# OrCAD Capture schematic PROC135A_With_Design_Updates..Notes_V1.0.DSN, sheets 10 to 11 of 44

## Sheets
10 10. PERIPHERAL POWER SUPPLY-1: size C; title: PERIPHERAL POWER SUPPLY -1
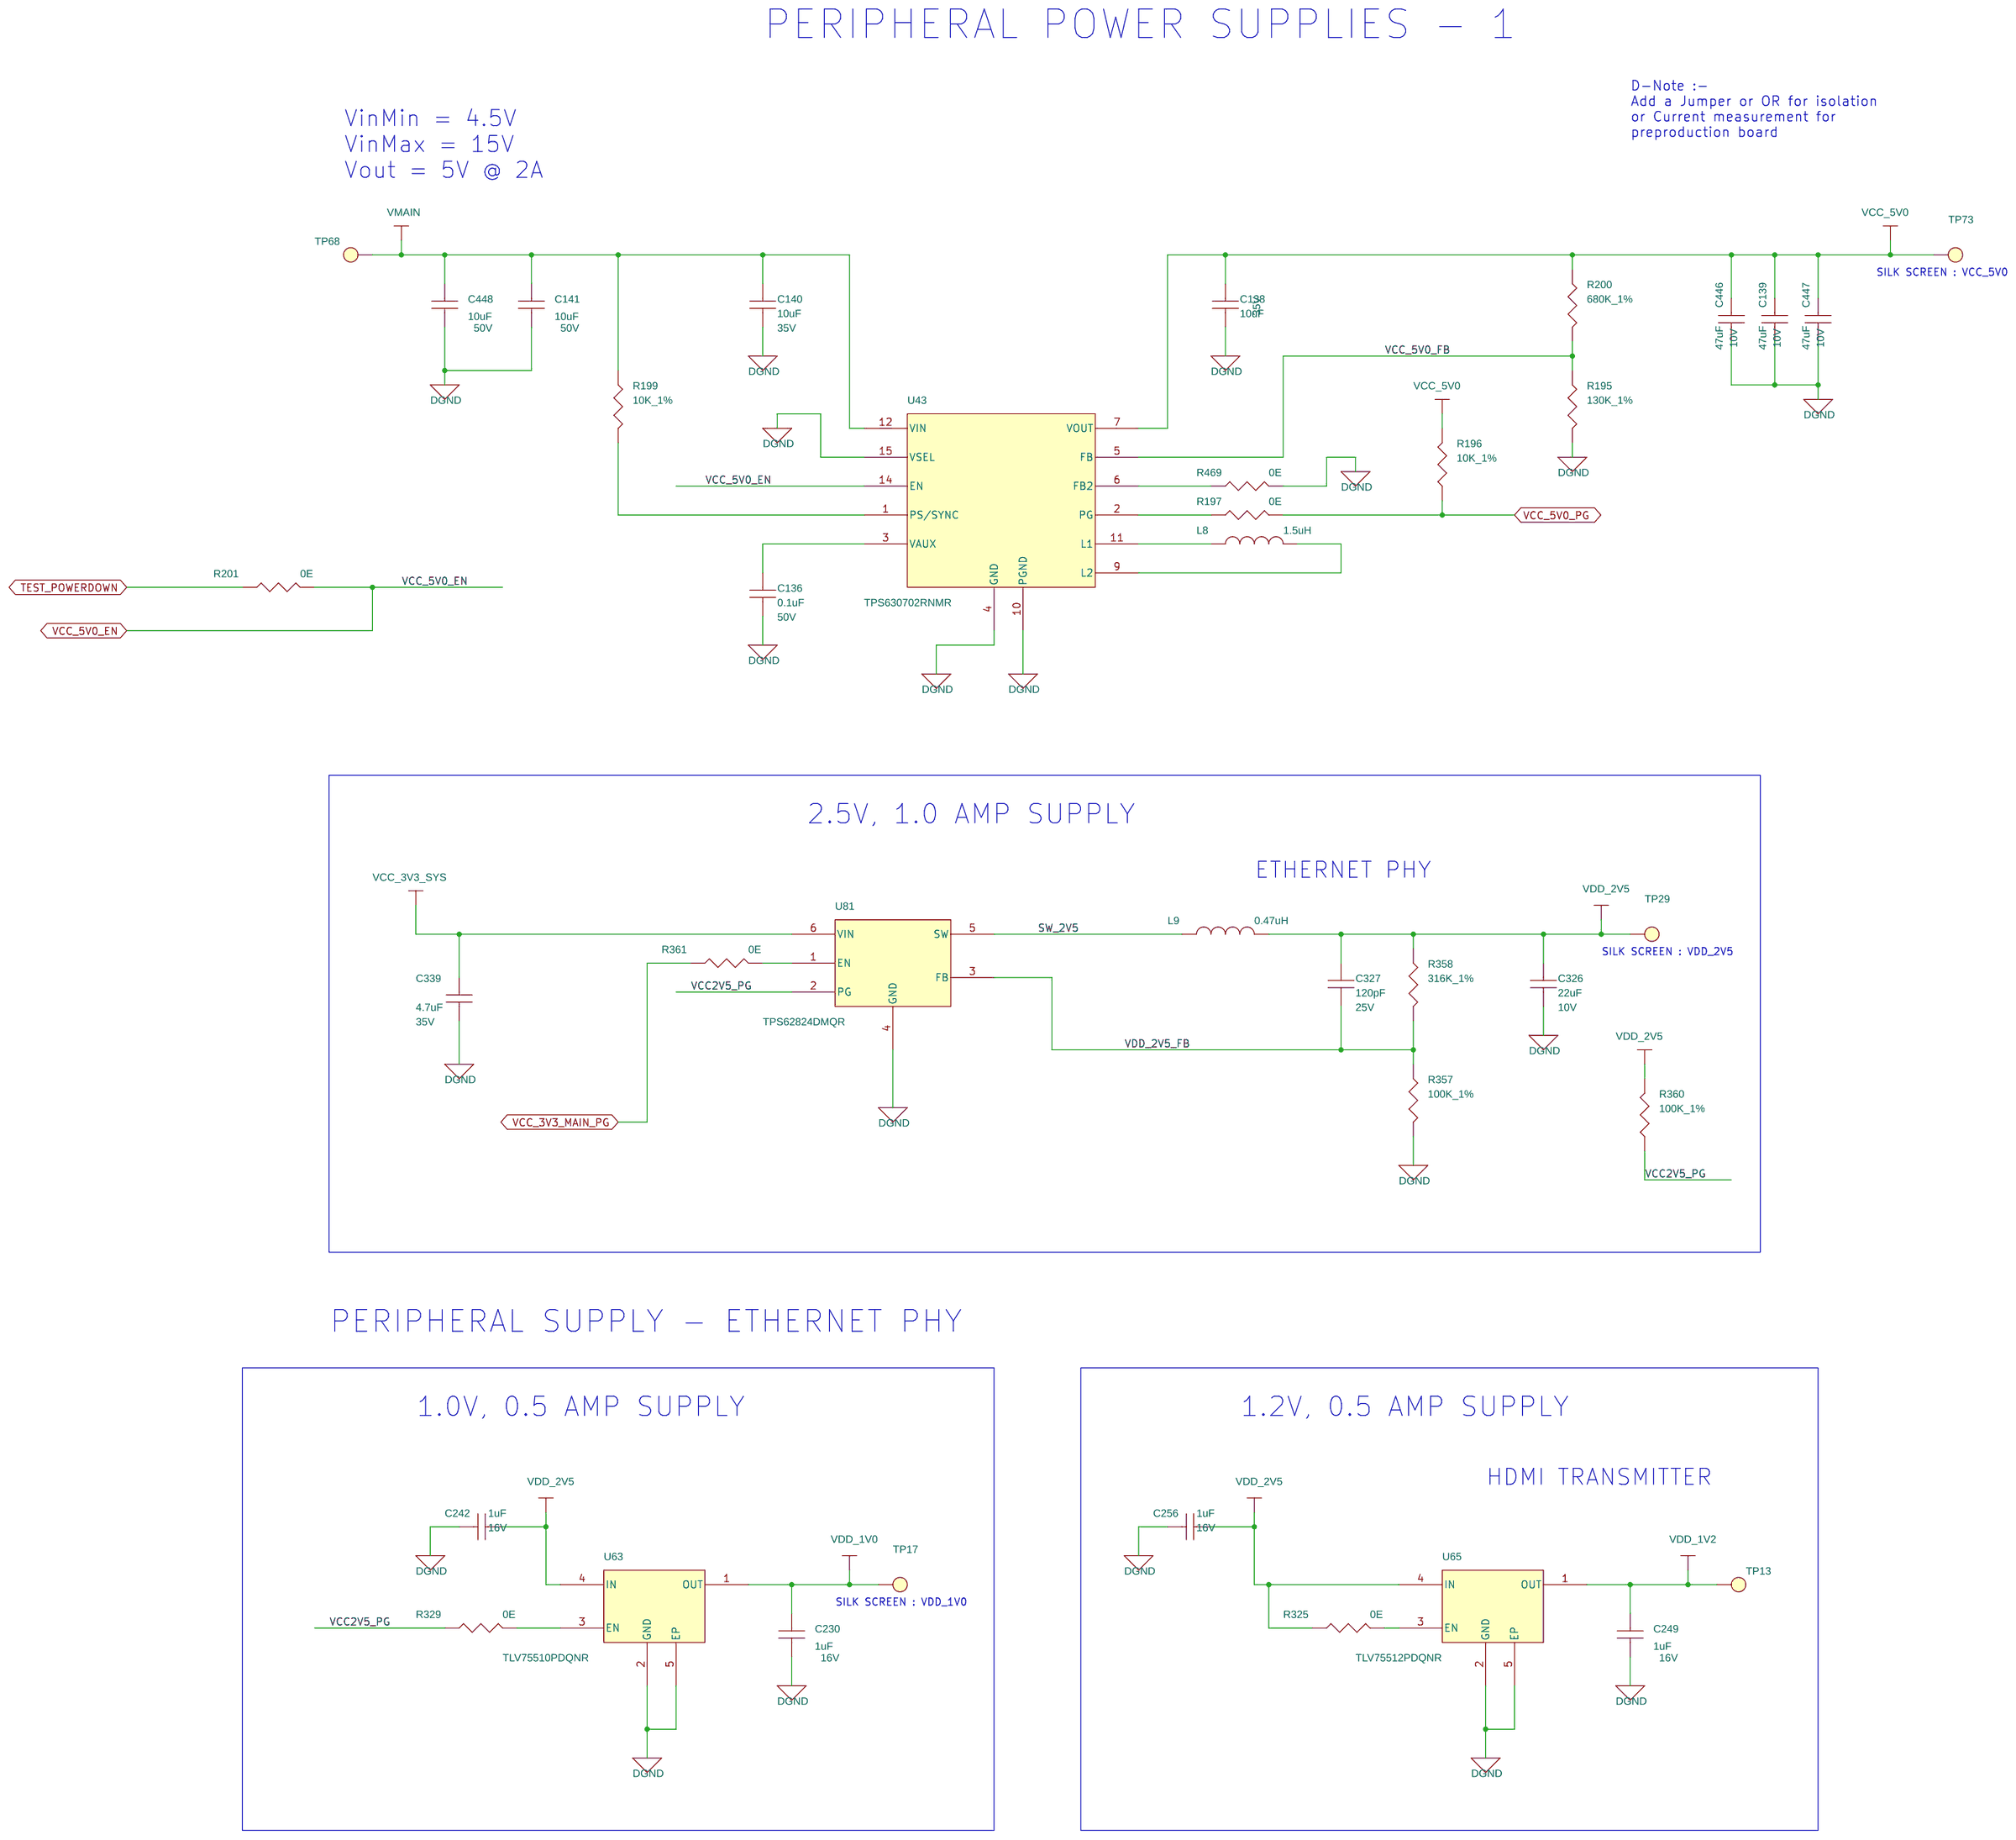
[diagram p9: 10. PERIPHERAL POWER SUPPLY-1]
11 11. PERIPHERAL POWER SUPPLY-2: size C; title: PERIPHERAL POWER SUPPLY-2
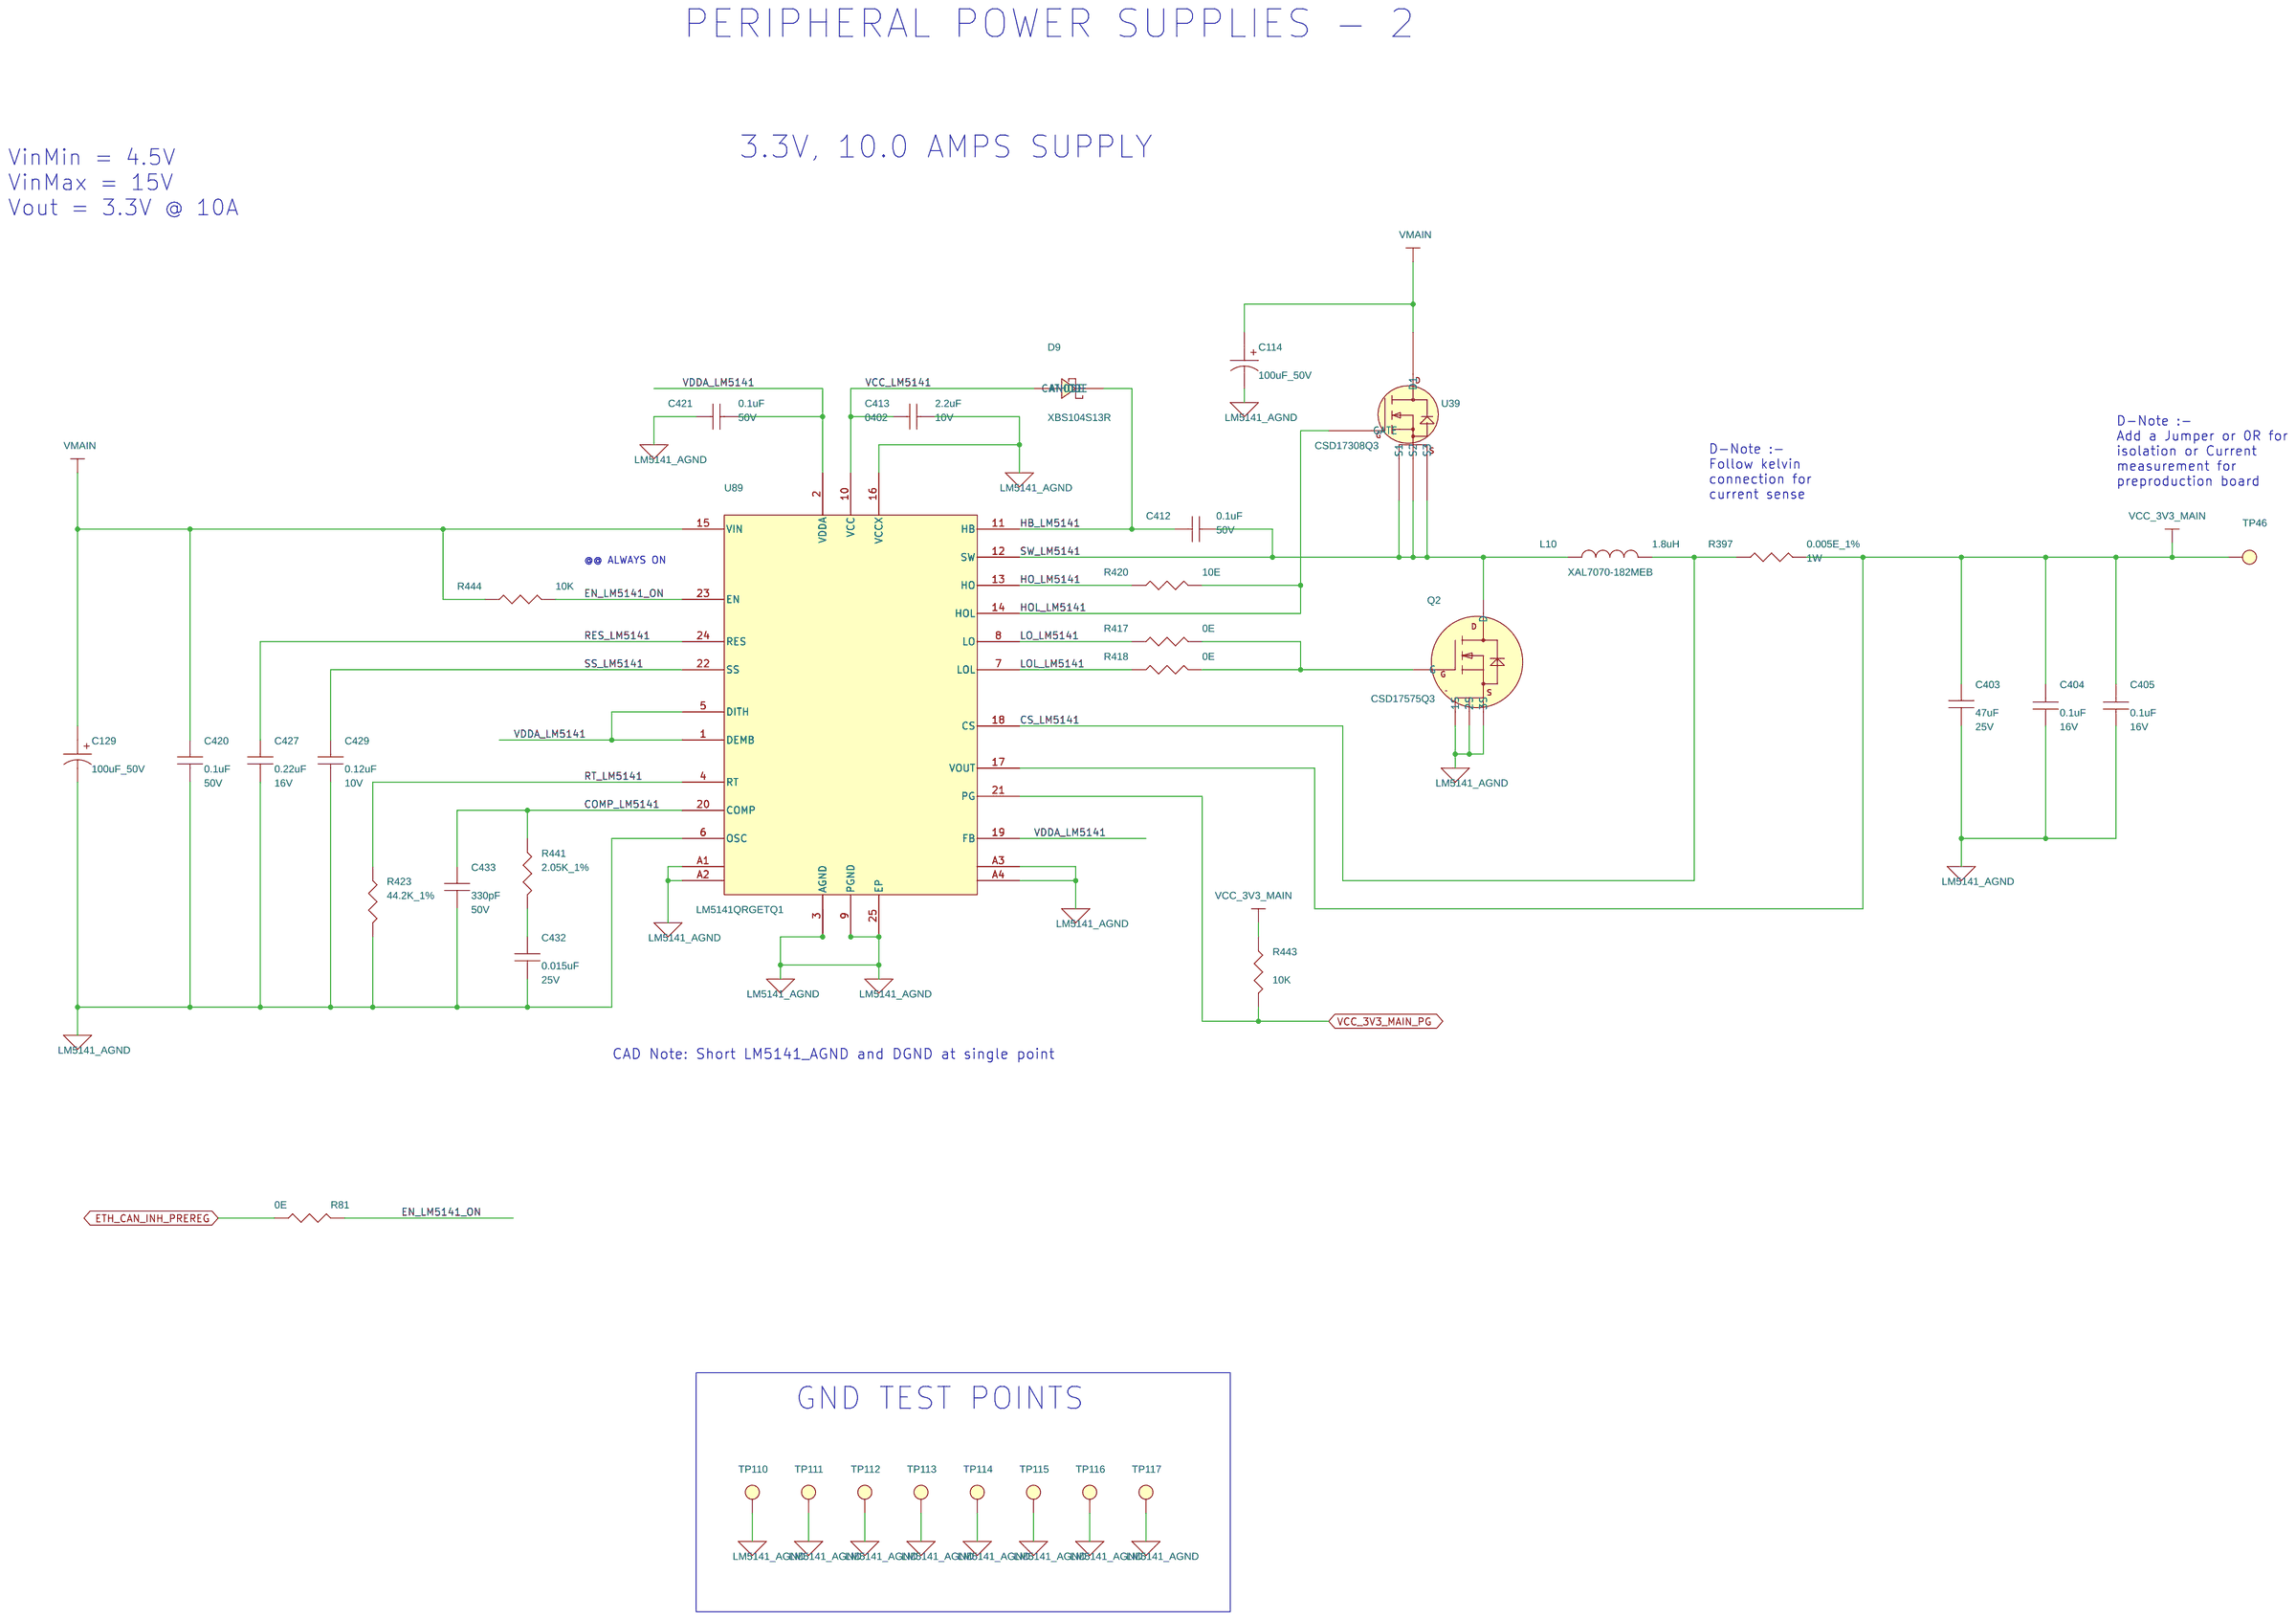
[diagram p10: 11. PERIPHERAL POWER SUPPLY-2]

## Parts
sheet 10. PERIPHERAL POWER SUPPLY-1
C136  0.1uF  [CAP0402_0-75]
C138  10uF  [CAP0603_1]
C139  47uF  [CAP0805_1-5]
C140  10uF  [CAP0603_1]
C141  10uF  [CAP0805_1-5]
C230  1uF  [CAP0201_0-5]
C242  1uF  [CAP0201_0-5]
C249  1uF  [CAP0201_0-5]
C256  1uF  [CAP0201_0-5]
C326  22uF  [CAP0603_1]
C327  120pF  [CAP0201_0-5]
C339  4.7uF  [CAP0603_1]
C446  47uF  [CAP0805_1-5]
C447  47uF  [CAP0805_1-5]
C448  10uF  [CAP0805_1-5]
L8  1.5uH  [IND_XFL4020_170X170_SMD_2-1]
L9  0.47uH  [IND0806_1-2]
R195  130K_1%  [RES0402_0-5]
R196  10K_1%  [RES0201_0-5]
R197  0E  [RES0201_0-5]
R199  10K_1%  [RES0201_0-5]
R200  680K_1%  [RES0402_0-5]
R201  0E  [RES0201_0-5]
R325  0E  [RES0201_0-5]
R329  0E  [RES0201_0-5]
R357  100K_1%  [RES0402_0-5]
R358  316K_1%  [RES0402_0-5]
R360  100K_1%  [RES0402_0-5]
R361  0E  [RES0201_0-5]
R469  0E  [RES0201_0-5]
TP13  TP20_SMD  [TP20_SMD]
TP17  TP20_SMD  [TP20_SMD]
TP29  TP20_SMD  [TP20_SMD]
TP68  TP20_SMD  [TP20_SMD]
TP73  TP20_SMD  [TP20_SMD]
U43  TPS630702RNMR  [VQFNHR15_TPS630701_100X120_1]
U63  TLV75510PDQNR  [X2SON4_TLV71318P_40X40_0-4]
U65  TLV75512PDQNR  [X2SON4_TLV71318P_40X40_0-4]
U81  TPS62824DMQR  [VSONHR6_TPS62826_60X60_1]
sheet 11. PERIPHERAL POWER SUPPLY-2
C114  100uF_50V  [CAPAE_FCASE_10-5]
C129  100uF_50V  [CAPAE_FCASE_10-5]
C403  47uF  [CAP1206_2]
C404  0.1uF  [CAP0201_0-5]
C405  0.1uF  [CAP0201_0-5]
C412  0.1uF  [CAP0402_0-75]
C413  2.2uF  [CAP0402_0-75]
C420  0.1uF  [CAP0402_0-75]
C421  0.1uF  [CAP0402_0-75]
C427  0.22uF  [CAP0402_0-75]
C429  0.12uF  [CAP0603_1]
C432  0.015uF  [CAP0402_0-75]
C433  330pF  [CAP0402_0-75]
D9  XBS104S13R  [DIO_SOD323_1]
L10  1.8uH  [IND_XAL7070_300X310_SMD_7]
Q2  CSD17575Q3  [VSON8_CSD173_130X130_1-1]
R81  0E  [RES0201_0-5]
R397  0.005E_1%  [RES1206_1]
R417  0E  [RES0402_0-5]
R418  0E  [RES0402_0-5]
R420  10E  [RES0402_0-5]
R423  44.2K_1%  [RES0402_0-5]
R441  2.05K_1%  [RES0402_0-5]
R443  10K  [RES0402_0-5]
R444  10K  [RES0402_0-5]
TP46  TP20_SMD  [TP20_SMD]
TP110  THRU HOLE  [TP_40X65]
TP111  THRU HOLE  [TP_40X65]
TP112  THRU HOLE  [TP_40X65]
TP113  THRU HOLE  [TP_40X65]
TP114  THRU HOLE  [TP_40X65]
TP115  TP40_SMD  [TP40_SMD]
TP116  TP40_SMD  [TP40_SMD]
TP117  TP40_SMD  [TP40_SMD]
U39  CSD17308Q3  [VSON8_CSD173_130X130]
U89  LM5141QRGETQ1  [VQFN24_LM5141_160X160_1]

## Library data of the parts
C136 = CAP: CAP CERAMIC 0.1uF 50V 10% X7R 0402; Chkd/date: MANIRAJA/261020; Crtd /date: ALVY/211020; Custom_Duty: 15%; Customs_HS_Code: 85322990; Distributor_name: DIGIKEY; Distributor_part_number: 490-10700-1-ND; Footprint Path: Y:\MIS_DATABASE\Library\ALTIUM_TOOL\PCB_FOOTPRINTS\Altium_Footprint_Lib.PcbLib; Height: 0.55MM; Library Path: Y:\MIS_DATABASE\Library\ALTIUM_TOOL\SCHEMATICS_PARTS\MS_DISCRETE_Library.schlib; Mfr_name: MURATA; Mfr_part_number: GRM155R71H104KE14D; Mistral Part No: 120011100014-R; Package: 0402; Part_type: CAPACITORS\CERAMIC; Project: J7_CP; RoHS: RoHS; Temperature: -55°C+125°C; Tolerance: 10%; Voltage: 50V; Wattage: NA; Weight: 3.1mg; Datasheet: Y:\MIS_DATABASE\DATASHEETS\CAPACITORS\GRM155R71H104KE14.PDF
C138 C140 = CAP: CAP CERAMIC 10uF 35V 20% X5R 0603; Chkd/date: MANIRAJA/170519; Crtd /date: ALVY/160519; Custom_Duty: 15%; Customs_HS_Code: 85322990; Distributor_name: DIGIKEY; Distributor_part_number: 490-13248-1-ND; Footprint Path: Y:\MIS_DATABASE\Library\ALTIUM_TOOL\PCB_FOOTPRINTS\Altium_Footprint_Lib.PcbLib; Height: 1.00MM; Library Path: Y:\MIS_DATABASE\Library\ALTIUM_TOOL\SCHEMATICS_PARTS\MS_DISCRETE_Library.schlib; Mfr_name: MURATA; Mfr_part_number: GRM188R6YA106MA73D; Mistral Part No: 120019050016-R; Package: 0603; Part_type: CAPACITORS\CERAMIC; Project: BRUKER_SD820_COMMONDO; RoHS: RoHS; Temperature: -55°C+85°C; Tolerance: 20%; Voltage: 35V; Wattage: NA; Weight: 9mg; Datasheet: Y:\MIS_DATABASE\DATASHEETS\CAPACITORS\GRM188R6YA106MA73.PDF
C139 C446 C447 = CAP: CAP CERAMIC 47uF 10V 20% X5R 0805; Chkd/date: MANIRAJA/181018; Crtd /date: ALVY/181018; Custom_Duty: 15%; Customs_HS_Code: 85322990; Distributor_name: DIGIKEY; Distributor_part_number: 490-9961-1-ND; Footprint Path: Y:\MIS_DATABASE\Library\ALTIUM_TOOL\PCB_FOOTPRINTS\Altium_Footprint_Lib.PcbLib; Height: 1.45MM; Library Path: Y:\MIS_DATABASE\Library\ALTIUM_TOOL\SCHEMATICS_PARTS\MS_DISCRETE_Library.schlib; Mfr_name: MURATA; Mfr_part_number: GRM21BR61A476ME15L; Mistral Part No: 120014100011-R; Package: 0805; Part_type: CAPACITORS\CERAMIC; Project: RFID_MODULE-DESIGN; RoHS: RoHS; Temperature: -55°C+85°C; Tolerance: 20%; Voltage: 10V; Wattage: NA; Weight: 9.5mg; Datasheet: Y:\MIS_DATABASE\DATASHEETS\CAPACITORS\GRM21BR61A476ME15L.PDF
C141 C448 = CAP: CAP CERAMIC 10uF 50V 10% X5R 0805; Chkd/date: MANIRAJA/010321; Crtd /date: ALVY/010321; Custom_Duty: 15%; Customs_HS_Code: 85322990; Distributor_name: DIGIKEY; Distributor_part_number: 490-18663-1-ND; Footprint Path: Y:\MIS_DATABASE\Library\ALTIUM_TOOL\PCB_FOOTPRINTS\Altium_Footprint_Lib.PcbLib; Height: 1.45MM; Library Path: Y:\MIS_DATABASE\Library\ALTIUM_TOOL\SCHEMATICS_PARTS\MS_DISCRETE_Library.schlib; Mfr_name: MURATA; Mfr_part_number: GRM21BR61H106KE43L; Mistral Part No: 120021030002-R; Package: 0805; Part_type: CAPACITORS\CERAMIC; Project: J7ES_SK_BRD; RoHS: RoHS; Temperature: -55°C+85°C; Tolerance: 10%; Voltage: 50V; Wattage: NA; Weight: 6.4mg; Datasheet: Y:\MIS_DATABASE\DATASHEETS\CAPACITORS\GRM21BR61H106KE43.PDF
C230 C242 C249 C256 = CAP: CAP CERAMIC 1uF 16V 20% X5R 0201; Chkd/date: MANIRAJA/300520; Crtd /date: ALVY/260520; Custom_Duty: 15%; Customs_HS_Code: 85322990; Distributor_name: DIGIKEY; Distributor_part_number: 490-18654-1-ND; Footprint Path: Y:\MIS_DATABASE\Library\ALTIUM_TOOL\PCB_FOOTPRINTS\Altium_Footprint_Lib.PcbLib; Height: 0.39MM; Library Path: Y:\MIS_DATABASE\Library\ALTIUM_TOOL\SCHEMATICS_PARTS\MS_DISCRETE_Library.schlib; Mfr_name: MURATA; Mfr_part_number: GRM033R61C105ME15D; Mistral Part No: 120018090038-R; Package: 0201; Part_type: CAPACITORS\CERAMIC; Project: QCS610_NANOSOM; RoHS: RoHS; Temperature: -55°C+85°C; Tolerance: 20%; Voltage: 16V; Wattage: NA; Weight: 0.33mg; Datasheet: Y:\MIS_DATABASE\DATASHEETS\CAPACITORS\GRM033R61C105ME15.PDF
C326 = CAP: CAP CERAMIC 22uF 10V 20% X5R 0603; Chkd/date: MANIRAJA/230118; Crtd /date: MANIRAJA/230118; Custom_Duty: 15%; Customs_HS_Code: 85322990; Distributor_name: DIGIKEY; Distributor_part_number: 490-10476-1-ND; Footprint Path: Y:\MIS_DATABASE\Library\ALTIUM_TOOL\PCB_FOOTPRINTS\Altium_Footprint_Lib.PcbLib; Height: 1.00MM; Library Path: Y:\MIS_DATABASE\Library\ALTIUM_TOOL\SCHEMATICS_PARTS\MS_DISCRETE_Library.schlib; Mfr_name: MURATA; Mfr_part_number: GRM188R61A226ME15D; Mistral Part No: 120014100009-R; Package: 0603; Part_type: CAPACITORS\CERAMIC; Project: TI_MAXIE_CPB; RoHS: RoHS; Temperature: -55°C+85°C; Tolerance: 20%; Voltage: 10V; Wattage: NA; Weight: 6.3mg; Datasheet: Y:\MIS_DATABASE\DATASHEETS\CAPACITORS\GRM188R61A226ME15.PDF
C327 = CAP: CAP CERAMIC 120pF 25V 10% X7R 0201; Chkd/date: ALVY/260821; Crtd /date: MANIRAJA/260821; Custom_Duty: 15%; Customs_HS_Code: 85322990; Distributor_name: DIGIKEY; Distributor_part_number: 490-3173-1-ND; Footprint Path: Y:\MIS_DATABASE\Library\ALTIUM_TOOL\PCB_FOOTPRINTS\Altium_Footprint_Lib.PcbLib; Height: 0.33MM; Library Path: Y:\MIS_DATABASE\Library\ALTIUM_TOOL\SCHEMATICS_PARTS\MS_DISCRETE_Library.schlib; Mfr_name: MURATA; Mfr_part_number: GRM033R71E121KA01D; Mistral Part No: 120021080009-R; Package: 0201; Part_type: CAPACITORS\CERAMIC; Project: TI_AM62x SKEVM_BRD; RoHS: RoHS; Temperature: -55°C+125°C; Tolerance: 10%; Voltage: 25V; Wattage: NA; Weight: 0.33mg; Datasheet: Y:\MIS_DATABASE\DATASHEETS\CAPACITORS\GRM033R71E121KA01.PDF
C339 = CAP: CAP CERAMIC 4.7uF 35V 20% X5R 0603; Chkd/date: MANIRAJA/120520; Crtd /date: ALVY/120520; Custom_Duty: 15%; Customs_HS_Code: 85322990; Distributor_name: DIGIKEY; Distributor_part_number: 490-11995-1-ND; Footprint Path: Y:\MIS_DATABASE\Library\ALTIUM_TOOL\PCB_FOOTPRINTS\Altium_Footprint_Lib.PcbLib; Height: 1.00MM; Library Path: Y:\MIS_DATABASE\Library\ALTIUM_TOOL\SCHEMATICS_PARTS\MS_DISCRETE_Library.schlib; Mfr_name: MURATA; Mfr_part_number: GRM188R6YA475ME15D; Mistral Part No: 120020050017-R; Package: 0603; Part_type: CAPACITORS\CERAMIC; Project: SD865_NANOSOM; RoHS: RoHS; Temperature: -55°C+85°C; Tolerance: 20%; Voltage: 35V; Wattage: NA; Weight: 6.3mg; Datasheet: Y:\MIS_DATABASE\DATASHEETS\CAPACITORS\GRM188R6YA475ME15.PDF
L8 = INDUCTOR: IND POWER 1.5uH 9.1A 20% SMD; Chkd/date: MANIRAJA/101019; Crtd /date: MANIRAJA/101019; Custom_Duty: 24%; Customs_HS_Code: 85437099; Distributor_name: MOUSER; Distributor_part_number: 994-XFL4020-152MEB; Footprint Path: Y:\MIS_DATABASE\Library\ALTIUM_TOOL\PCB_FOOTPRINTS\Altium_Footprint_Lib.PcbLib; Height: 2.10MM; Library Path: Y:\MIS_DATABASE\Library\ALTIUM_TOOL\SCHEMATICS_PARTS\MS_DISCRETE_Library.schlib; Mfr_name: COIL CRAFT; Mfr_part_number: XFL4020-152MEB; Mistral Part No: 130019100011-R; Package: SMD; Project: NPOL_UAIS_CONTROLLER-CARD; RoHS: RoHS; Temperature: -40°C+125°C; Tolerance: 20%; Voltage: NA; Wattage: NA; Weight: 169mg; Datasheet: Y:\MIS_DATABASE\DATASHEETS\DISCRETES\INDUCTORS\XFL4020.PDF
L9 = INDUCTOR: IND CHIP 0.47uH 4.5A 20% 0806; Chkd/date: MANIRAJA/121020; Crtd /date: ALVY/121020; Custom_Duty: 24%; Customs_HS_Code: 85437099; Distributor_name: DIGIKEY; Distributor_part_number: DFE201612E-R47M=P2-ND; Footprint Path: Y:\MIS_DATABASE\Library\ALTIUM_TOOL\PCB_FOOTPRINTS\Altium_Footprint_Lib.PcbLib; Height: 1.20MM; Library Path: Y:\MIS_DATABASE\Library\ALTIUM_TOOL\SCHEMATICS_PARTS\MS_DISCRETE_Library.schlib; Mfr_name: MURATA; Mfr_part_number: DFE201612E-R47M=P2; Mistral Part No: 130020100030-R; Package: 0806; Project: AM64X_SKEVM; RoHS: RoHS; Temperature: -40°C+125°C; Tolerance: 20%; Voltage: NA; Wattage: NA; Weight: 18.8mg; Datasheet: Y:\MIS_DATABASE\DATASHEETS\DISCRETES\INDUCTORS\DFE201612E.PDF
R195 = RESISTOR: RES 130K 1/10W 1% 0402; Chkd/date: MAZHAR/150611; Crtd /date: BAVISH/020611; Custom_Duty: 15%; Customs_HS_Code: 85332119; Distributor_name: DIGIKEY; Distributor_part_number: P130KLCT-ND; Footprint Path: Y:\MIS_DATABASE\Library\ALTIUM_TOOL\PCB_FOOTPRINTS\Altium_Footprint_Lib.PcbLib; Height: 0.40MM; Library Path: Y:\MIS_DATABASE\Library\ALTIUM_TOOL\SCHEMATICS_PARTS\MS_DISCRETE_Library.schlib; Mfr_name: PANASONIC-ECG; Mfr_part_number: ERJ-2RKF1303X; Mistral Part No: 110011060012-R; Package: 0402; Part_type: RESISTORS\FIXED; Project: AM4515_EVM_LCD; RoHS: RoHS; Temperature: -55°C+155°C; Tolerance: 1%; Voltage: NA; Wattage: 1/10W; Weight: 0.8mg; Datasheet: Y:\MIS_DATABASE\DATASHEETS\RESISTORS\PAN-ERJSER_NOV17.PDF
R196 R199 = RESISTOR: RES 10K 1/20W 1% 0201; Chkd/date: VASANTHA/270117; Crtd /date: MANIRAJA/270117; Custom_Duty: 15%; Customs_HS_Code: 85332119; Distributor_name: DIGIKEY; Distributor_part_number: 311-10.0KMCT-ND; Footprint Path: Y:\MIS_DATABASE\Library\ALTIUM_TOOL\PCB_FOOTPRINTS\Altium_Footprint_Lib.PcbLib; Height: 0.26MM; Library Path: Y:\MIS_DATABASE\Library\ALTIUM_TOOL\SCHEMATICS_PARTS\MS_DISCRETE_Library.schlib; Mfr_name: YAGEO AMERICA; Mfr_part_number: RC0201FR-0710KL; Mistral Part No: 110011040018-R; Package: 0201; Part_type: RESISTORS\FIXED; Project: GOLDEN-I LITE; RoHS: RoHS; Temperature: -55°C+125°C; Tolerance: 1%; Voltage: NA; Wattage: 1/20W; Weight: 0.17mg; Datasheet: Y:\MIS_DATABASE\DATASHEETS\RESISTORS\RCXXXXL-SER_MAR18.PDF
R197 R201 R325 R329 R361 R469 = RESISTOR: RES 0E 1/20W 5% 0201; Chkd/date: NAVEED/301214; Crtd /date: MUDDU/120710; Custom_Duty: 15%; Customs_HS_Code: 85332119; Distributor_name: DIGIKEY; Distributor_part_number: 311-0.0NCT-ND; Footprint Path: Y:\MIS_DATABASE\Library\ALTIUM_TOOL\PCB_FOOTPRINTS\Altium_Footprint_Lib.PcbLib; Height: 0.26MM; Library Path: Y:\MIS_DATABASE\Library\ALTIUM_TOOL\SCHEMATICS_PARTS\MS_DISCRETE_Library.schlib; Mfr_name: YAGEO AMERICA; Mfr_part_number: RC0201JR-070RL; Mistral Part No: 110010070067-R; Package: 0201; Part_type: RESISTORS\FIXED; Project: PB_BUGBASE; RoHS: RoHS; Temperature: -55°C+125°C; Tolerance: 5%; Voltage: NA; Wattage: 1/20W; Weight: 0.17mg; Datasheet: Y:\MIS_DATABASE\DATASHEETS\RESISTORS\RCXXXXL-SER_MAR18.PDF
R200 = RESISTOR: RES 680K 1/10W 1% 0402; Chkd/date: SUHAS/200411; Crtd /date: MAZHAR/180411; Custom_Duty: 15%; Customs_HS_Code: 85332119; Distributor_name: DIGIKEY; Distributor_part_number: P680KLCT-ND; Footprint Path: Y:\MIS_DATABASE\Library\ALTIUM_TOOL\PCB_FOOTPRINTS\Altium_Footprint_Lib.PcbLib; Height: 0.40MM; Library Path: Y:\MIS_DATABASE\Library\ALTIUM_TOOL\SCHEMATICS_PARTS\MS_DISCRETE_Library.schlib; Mfr_name: PANASONIC-ECG; Mfr_part_number: ERJ-2RKF6803X; Mistral Part No: 110011040004-R; Package: 0402; Part_type: RESISTORS\FIXED; Project: AM4515_EVM_LCD; RoHS: RoHS; Temperature: -55°C+155°C; Tolerance: 1%; Voltage: NA; Wattage: 1/10W; Weight: 0.8mg; Datasheet: Y:\MIS_DATABASE\DATASHEETS\RESISTORS\PAN-ERJSER_NOV17.PDF
R357 R360 = RESISTOR: RES 100K 1/10W 1% 0402; Chkd/date: VASANTHA/201216; Crtd /date: MAZHAR/130306; Custom_Duty: 15%; Customs_HS_Code: 85332119; Distributor_name: DIGIKEY; Distributor_part_number: P100KLCT-ND; Footprint Path: Y:\MIS_DATABASE\Library\ALTIUM_TOOL\PCB_FOOTPRINTS\Altium_Footprint_Lib.PcbLib; Height: 0.40MM; Library Path: Y:\MIS_DATABASE\Library\ALTIUM_TOOL\SCHEMATICS_PARTS\MS_DISCRETE_Library.schlib; Mfr_name: PANASONIC-ECG; Mfr_part_number: ERJ-2RKF1003X; Mistral Part No: 110009030187-R; Package: 0402; Part_type: RESISTORS\FIXED; Project: J32; RoHS: RoHS; Temperature: -55°C+155°C; Tolerance: 1%; Voltage: NA; Wattage: 1/10W; Weight: 0.8mg; Datasheet: Y:\MIS_DATABASE\DATASHEETS\RESISTORS\PAN-ERJSER_NOV17.PDF
R358 = RESISTOR: RES 316K 1/10W 1% 0402; Chkd/date: MAZHAR/110310; Crtd /date: MUDDU/080310; Custom_Duty: 15%; Customs_HS_Code: 85332119; Distributor_name: DIGIKEY; Distributor_part_number: P316KLCT-ND; Footprint Path: Y:\MIS_DATABASE\Library\ALTIUM_TOOL\PCB_FOOTPRINTS\Altium_Footprint_Lib.PcbLib; Height: 0.40MM; Library Path: Y:\MIS_DATABASE\Library\ALTIUM_TOOL\SCHEMATICS_PARTS\MS_DISCRETE_Library.schlib; Mfr_name: PANASONIC-ECG; Mfr_part_number: ERJ-2RKF3163X; Mistral Part No: 110010030027-R; Package: 0402; Part_type: RESISTORS\FIXED; Project: VME_DSP_SUITE; RoHS: RoHS; Temperature: -55°C+155°C; Tolerance: 1%; Voltage: NA; Wattage: 1/10W; Weight: 0.8mg; Datasheet: Y:\MIS_DATABASE\DATASHEETS\RESISTORS\PAN-ERJSER_NOV17.PDF
TP13 TP68 TP73 = TESTPOINT: TESTPOINT CIR 20 SMD; Chkd/date: SHREESHAIL/171006; Crtd /date: MAZHAR/171006; Custom_Duty: NA; Customs_HS_Code: NA; Distributor_name: NA; Distributor_part_number: NA; Footprint Path: Y:\MIS_DATABASE\Library\ALTIUM_TOOL\PCB_FOOTPRINTS\Altium_Footprint_Lib.PcbLib; Height: NA; Library Path: Y:\MIS_DATABASE\Library\ALTIUM_TOOL\SCHEMATICS_PARTS\MS_DISCRETE_Library.schlib; MECHANICAL 3D STEP FILE: NA; Mfr_name: LOCAL; Mistral Part No: NA; Package: SMD; Project: BT MODULE_CSRBC04; RoHS: NA; Temperature: NA; Tolerance: NA; Voltage: NA; Wattage: NA; Weight: NA; Datasheet: NA
TP17 TP29 TP46 = TESTPOINT: TESTPOINT CIR 20 SMD; Chkd/date: SHREESHAIL/171006; Crtd /date: MAZHAR/171006; Custom_Duty: NA; Customs_HS_Code: NA; Distributor_name: NA; Distributor_part_number: NA; Footprint Path: Y:\MIS_DATABASE\Library\ALTIUM_TOOL\PCB_FOOTPRINTS\Altium_Footprint_Lib.PcbLib; Height: NA; Library Path: Y:\MIS_DATABASE\Library\ALTIUM_TOOL\SCHEMATICS_PARTS\MS_DISCRETE_Library.schlib; MECHANICAL 3D STEP FILE: NA; Manufacturer: LOCAL; Mfr_name: LOCAL; Mistral Part No: NA; Package: SMD; Project: BT MODULE_CSRBC04; RoHS: NA; Temperature: NA; Tolerance: NA; Voltage: NA; Wattage: NA; Weight: NA; Datasheet: NA
U43 = TPS630701_VQFN-HR15: IC ADJ BUCK-BOOST CONVERTER WITH 3.6A SWITCH CURRENT VQFN-HR15; Chkd/date: ALVY/250122; Crtd /date: MANIRAJA/250122; Custom_Duty: 15%; Customs_HS_Code: 85423100; Distributor_name: DIGIKEY; Distributor_part_number: 296-TPS630702RNMRCT-ND; Footprint Path: Y:\MIS_DATABASE\Library\ALTIUM_TOOL\PCB_FOOTPRINTS\Altium_Footprint_Lib.PcbLib; Height: 1.00MM; Library Path: Y:\MIS_DATABASE\Library\ALTIUM_TOOL\SCHEMATICS_PARTS\MS_MISCPOWER_Library.schlib; Mfr_name: TEXAS INSTRUMENTS; Mistral Part No: 142022010015-R; Package: VQFN-HR15; Part_type: ICS\POWER\DC-DC CONVERTER; Project: AM62X_SKEVM; RoHS: RoHS; Temperature: -40°C+125°C; Tolerance: NA; Voltage: NA; Wattage: NA; Weight: 17.7mg; Datasheet: Y:\MIS_DATABASE\DATASHEETS\ICS\POWER\TPS630701X.PDF
U63 = TLV71318PDQNR_X2SON4: IC 500mA 1V LOW IQ LDO REGULATOR X2SON-4; Chkd/date: MANIRAJA/240821; Crtd /date: ALVY/240821; Custom_Duty: 15%; Customs_HS_Code: 85423100; Distributor_name: DIGIKEY; Distributor_part_number: 296-51782-1-ND; Footprint Path: Y:\MIS_DATABASE\Library\ALTIUM_TOOL\PCB_FOOTPRINTS\Altium_Footprint_Lib.PcbLib; Height: 0.40MM; Library Path: Y:\MIS_DATABASE\Library\ALTIUM_TOOL\SCHEMATICS_PARTS\MS_MISCPOWER_Library.schlib; Mfr_name: TEXAS INSTRUMENTS; Mistral Part No: 142021080018-R; Package: X2SON-4; Part_type: ICS\POWER\VOLTAGE REGULATOR; Project: TI_AM62x SKEVM_BRD; RoHS: RoHS; Temperature: -40°C+125°C; Tolerance: NA; Voltage: NA; Wattage: NA; Weight: 1.1mg; Datasheet: Y:\MIS_DATABASE\DATASHEETS\ICS\POWER\TLV755P.PDF
U65 = TLV71318PDQNR_X2SON4: IC 500mA 1.2V LOW IQ LDO REGULATOR X2SON-4; Chkd/date: MANIRAJA/290921; Crtd /date: ALVY/290921; Custom_Duty: 15%; Customs_HS_Code: 85423100; Distributor_name: DIGIKEY; Distributor_part_number: 296-51785-1-ND; Footprint Path: Y:\MIS_DATABASE\Library\ALTIUM_TOOL\PCB_FOOTPRINTS\Altium_Footprint_Lib.PcbLib; Height: 0.40MM; Library Path: Y:\MIS_DATABASE\Library\ALTIUM_TOOL\SCHEMATICS_PARTS\MS_MISCPOWER_Library.schlib; Mfr_name: TEXAS INSTRUMENTS; Mistral Part No: 142021090022-R; Package: X2SON-4; Part_type: ICS\POWER\VOLTAGE REGULATOR; Project: TI_AM62x SKEVM_BRD; RoHS: RoHS; Temperature: -40°C+125°C; Tolerance: NA; Voltage: NA; Wattage: NA; Weight: 1.1mg; Datasheet: Y:\MIS_DATABASE\DATASHEETS\ICS\POWER\TLV755P.PDF
U81 = TPS62827DMQR_VSONHR6: IC 1A ADJ STEP-DOWN CONVERTER WITH 1% OUTPUT ACCURACY VSON-HR6; Chkd/date: ALVY/071021; Crtd /date: MANIRAJA/071021; Custom_Duty: 15%; Customs_HS_Code: 85423100; Distributor_name: NA; Distributor_part_number: NA; Footprint Path: Y:\MIS_DATABASE\Library\ALTIUM_TOOL\PCB_FOOTPRINTS\Altium_Footprint_Lib.PcbLib; Height: 1.00MM; Library Path: Y:\MIS_DATABASE\Library\ALTIUM_TOOL\SCHEMATICS_PARTS\MS_MISCPOWER_Library.schlib; Mfr_name: TEXAS INSTRUMENTS; Mistral Part No: 142021100006-R; Package: VSON-HR6; Part_type: ICS\POWER\DC-DC CONVERTER; Project: TI_AM62x SKEVM_BRD; RoHS: RoHS; Temperature: -40°C+125°C; Tolerance: NA; Voltage: NA; Wattage: NA; Weight: NA; Datasheet: Y:\MIS_DATABASE\DATASHEETS\ICS\POWER\TPS6282XX-DEC2020.PDF
C114 C129 = CAP_POL: CAP ELECTROLYTIC 100uF 50V 20% CASE_8383; Chkd/date: MANIRAJA/221021; Crtd /date: TAMILARASU/221021; Custom_Duty: 15%; Customs_HS_Code: 85322990; Distributor_name: DIGIKEY; Distributor_part_number: 3372-UT107M050HFKTATR-ND; Footprint Path: Y:\MIS_DATABASE\Library\ALTIUM_TOOL\PCB_FOOTPRINTS\Altium_Footprint_Lib.PcbLib; Footprint Ref: CAPAE_D8CASE_8; Height: 10.50MM; Library Path: Y:\MIS_DATABASE\Library\ALTIUM_TOOL\SCHEMATICS_PARTS\MS_DISCRETE_Library.schlib; Mfr_name: NEXTGEN; Mfr_part_number: UT107M050HFKTA; Mistral Part No: 120021100004-R; Package: CASE_8383; Part_type: CAPACITORS\ELECTROLYTIC; Project: TI_J7AEP_SK_BRD; RoHS: RoHS; Temperature: -55°C+105°C; Tolerance: 20%; Voltage: 50V; Wattage: NA; Weight: NA; Datasheet: Y:\MIS_DATABASE\DATASHEETS\CAPACITORS\UT107M050HFKTA.PDF
C403 = CAP: CAP CERAMIC 47uF 25V 20% X5R 1206; Chkd/date: VASANTHA/261214; Crtd /date: USMAN/160513; Custom_Duty: 15%; Customs_HS_Code: 85322990; Distributor_name: DIGIKEY; Distributor_part_number: 445-8047-1-ND; Footprint Path: Y:\MIS_DATABASE\Library\ALTIUM_TOOL\PCB_FOOTPRINTS\Altium_Footprint_Lib.PcbLib; Height: 1.80MM; Library Path: Y:\MIS_DATABASE\Library\ALTIUM_TOOL\SCHEMATICS_PARTS\MS_DISCRETE_Library.schlib; Mfr_name: TDK CORPORATION; Mfr_part_number: C3216X5R1E476M160AC; Mistral Part No: 120013050002-R; Package: 1206; Part_type: CAPACITORS\CERAMIC; Project: ERP; RoHS: RoHS; Temperature: -55°C+85°C; Tolerance: 20%; Voltage: 25V; Wattage: NA; Weight: 16.2mg; Datasheet: Y:\MIS_DATABASE\DATASHEETS\CAPACITORS\TDK_C-SER-JUL17.PDF
C404 C405 = CAP: CAP CERAMIC 0.1uF 16V 10% X7S AUTO 0201; Chkd/date: MANIRAJA/110321; Crtd /date: ALVY/110321; Custom_Duty: 15%; Customs_HS_Code: 85322990; Distributor_name: DIGIKEY; Distributor_part_number: 490-GRT033C71C104KE01DTR-ND; Height: 0.33MM; Mfr_name: MURATA; Mfr_part_number: GRT033C71C104KE01D; Mistral Part No: 120021030007-R; Package: 0201; Part_type: CAPACITORS\CERAMIC; Project: J7ES_SK_BRD; RoHS: RoHS; Temperature: -55°C+125°C; Tolerance: 10%; Voltage: 16V; Wattage: NA; Weight: 330mg; Datasheet: Y:\MIS_DATABASE\DATASHEETS\CAPACITORS\GRT033C71C104KE01.PDF
C412 C420 C421 = CAP: CAP CERAMIC 0.1uF 50V 10% X7R AUTO 0402; Chkd/date: MANIRAJA/250221; Crtd /date: ALVY/240221; Custom_Duty: 15%; Customs_HS_Code: 85322990; Distributor_name: MOUSER; Distributor_part_number: 81-GRT155R71H104KE1D; Footprint Path: Y:\MIS_DATABASE\Library\ALTIUM_TOOL\PCB_FOOTPRINTS\Altium_Footprint_Lib.PcbLib; Height: 0.55MM; Library Path: Y:\MIS_DATABASE\Library\ALTIUM_TOOL\SCHEMATICS_PARTS\MS_DISCRETE_Library.schlib; Mfr_name: MURATA; Mfr_part_number: GRT155R71H104KE01D; Mistral Part No: 120019030005-R; Package: 0402; Part_type: CAPACITORS\CERAMIC; Project: TI_DRA821 SK EVM BRD; RoHS: RoHS; Temperature: -55°C+125°C; Tolerance: 10%; Voltage: 50V; Wattage: NA; Weight: NA; Datasheet: Y:\MIS_DATABASE\DATASHEETS\CAPACITORS\GRT155R71H104KE01.PDF
C413 = CAP: CAP CERAMIC 2.2uF 10V 10% X5R AUTO 0402; Chkd/date: MANIRAJA/250221; Crtd /date: ALVY/240221; Custom_Duty: 15%; Customs_HS_Code: 85322990; Distributor_name: DIGIKEY; Distributor_part_number: 490-12253-1-ND; Footprint Path: Y:\MIS_DATABASE\Library\ALTIUM_TOOL\PCB_FOOTPRINTS\Altium_Footprint_Lib.PcbLib; Height: 0.55MM; Library Path: Y:\MIS_DATABASE\Library\ALTIUM_TOOL\SCHEMATICS_PARTS\MS_DISCRETE_Library.schlib; Mfr_name: MURATA; Mfr_part_number: GRT155R61A225KE01D; Mistral Part No: 120021020031-R; Package: 0402; Part_type: CAPACITORS\CERAMIC; Project: TI_DRA821 SK EVM BRD; RoHS: RoHS; Temperature: -55°C+85°C; Tolerance: 10%; Voltage: 10V; Wattage: NA; Weight: 1.5mg; Datasheet: Y:\MIS_DATABASE\DATASHEETS\CAPACITORS\GRT155R61A225KE01.PDF
C427 = CAP: CAP CERAMIC 0.22uF 16V 10% X7R AUTO 0402; Chkd/date: MANIRAJA/031219; Crtd /date: ALVY/021219; Custom_Duty: 15%; Customs_HS_Code: 85322990; Distributor_name: DIGIKEY; Distributor_part_number: 490-10671-1-ND; Footprint Path: Y:\MIS_DATABASE\Library\ALTIUM_TOOL\PCB_FOOTPRINTS\Altium_Footprint_Lib.PcbLib; Height: 0.55MM; Library Path: Y:\MIS_DATABASE\Library\ALTIUM_TOOL\SCHEMATICS_PARTS\MS_DISCRETE_Library.schlib; Mfr_name: MURATA; Mfr_part_number: GCM155R71C224KE02D; Mistral Part No: 120019020006-R; Package: 0402; Part_type: CAPACITORS\CERAMIC; Project: GRACO_PLC_EXPN BOARD; RoHS: RoHS; Temperature: -55°C+125°C; Tolerance: 10%; Voltage: 16V; Wattage: NA; Weight: 12mg; Datasheet: Y:\MIS_DATABASE\DATASHEETS\CAPACITORS\MURATA-GCM-SER.PDF
C429 = CAP: CAP CERAMIC 0.12uF 10V 10% X7R 0603; Chkd/date: MANIRAJA/080519; Crtd /date: ALVY/080519; Custom_Duty: 15%; Customs_HS_Code: 85322990; Distributor_name: DIGIKEY; Distributor_part_number: 311-4056-1-ND; Footprint Path: Y:\MIS_DATABASE\Library\ALTIUM_TOOL\PCB_FOOTPRINTS\Altium_Footprint_Lib.PcbLib; Height: 0.90MM; Library Path: Y:\MIS_DATABASE\Library\ALTIUM_TOOL\SCHEMATICS_PARTS\MS_DISCRETE_Library.schlib; Mfr_name: YAGEO AMERICA; Mfr_part_number: CC0603KRX7R6BB124; Mistral Part No: 120019050003-R; Package: 0603; Part_type: CAPACITORS\CERAMIC; Project: BRUKER_SD820_COMMONDO; RoHS: RoHS; Temperature: -55°C+125°C; Tolerance: 10%; Voltage: 10V; Wattage: NA; Weight: 2mg; Datasheet: Y:\MIS_DATABASE\DATASHEETS\CAPACITORS\YACC-X7R.PDF
C432 = CAP: CAP CERAMIC 0.015uF 25V 10% X7R AUTO 0402; Chkd/date: MANIRAJA/250221; Crtd /date: ALVY/240221; Custom_Duty: 15%; Customs_HS_Code: 85322990; Distributor_name: DIGIKEY; Distributor_part_number: 490-17756-1-ND; Footprint Path: Y:\MIS_DATABASE\Library\ALTIUM_TOOL\PCB_FOOTPRINTS\Altium_Footprint_Lib.PcbLib; Height: 0.55MM; Library Path: Y:\MIS_DATABASE\Library\ALTIUM_TOOL\SCHEMATICS_PARTS\MS_DISCRETE_Library.schlib; Mfr_name: MURATA; Mfr_part_number: GCM155R71E153KA55D; Mistral Part No: 120021020036-R; Package: 0402; Part_type: CAPACITORS\CERAMIC; Project: TI_DRA821 SK EVM BRD; RoHS: RoHS; Temperature: -55°C+125°C; Tolerance: 10%; Voltage: 25V; Wattage: NA; Weight: 6mg; Datasheet: Y:\MIS_DATABASE\DATASHEETS\CAPACITORS\GCM155R71E153KA55.PDF
C433 = CAP: CAP CERAMIC 330pF 50V 5% C0G(NP0) AUTO 0402; Chkd/date: MANIRAJA/250221; Crtd /date: ALVY/240221; Custom_Duty: 15%; Customs_HS_Code: 85322990; Distributor_name: MOUSER; Distributor_part_number: 81-GRT1555C1H331JA2D; Footprint Path: Y:\MIS_DATABASE\Library\ALTIUM_TOOL\PCB_FOOTPRINTS\Altium_Footprint_Lib.PcbLib; Height: 0.55MM; Library Path: Y:\MIS_DATABASE\Library\ALTIUM_TOOL\SCHEMATICS_PARTS\MS_DISCRETE_Library.schlib; Mfr_name: MURATA; Mfr_part_number: GRT1555C1H331JA02D; Mistral Part No: 120019050019-R; Package: 0402; Part_type: CAPACITORS\CERAMIC; Project: TI_DRA821 SK EVM BRD; RoHS: RoHS; Temperature: -55°C+125°C; Tolerance: 5%; Voltage: 50V; Wattage: NA; Weight: 3.1mg; Datasheet: Y:\MIS_DATABASE\DATASHEETS\CAPACITORS\GRT1555C1H331JA02.PDF
D9 = DIODE_SCHOTTKY: DIODE SCHOTTKY 40V 1A SOD323A; Chkd/date: MANIRAJA/150218; Crtd /date: ALVY/150218; Custom_Duty: 24%; Customs_HS_Code: 85437099; Distributor_name: DIGIKEY; Distributor_part_number: 893-1188-1-ND; Footprint Path: Y:\MIS_DATABASE\Library\ALTIUM_TOOL\PCB_FOOTPRINTS\Altium_Footprint_Lib.PcbLib; Height: 1.00MM; Library Path: Y:\MIS_DATABASE\Library\ALTIUM_TOOL\SCHEMATICS_PARTS\MS_DISCRETE_Library.schlib; Mfr_name: TOREX; Mfr_part_number: XBS104S13R-G; Mistral Part No: 130018020038-R; Package: SOD323; Part_type: DIODE\SCHOTTKY; Project: TI_MAXIE_CPB; RoHS: RoHS; Temperature: NA; Tolerance: NA; Voltage: 40V; Wattage: NA; Weight: NA; Datasheet: Y:\MIS_DATABASE\DATASHEETS\DISCRETES\DIODES\XBS104S13R-G.PDF
L10 = INDUCTOR: IND POWER 1.8uH 21A 20% SMD; Chkd/date: ALVY/221019; Crtd /date: MANIRAJA/221019; Custom_Duty: 24%; Customs_HS_Code: 85437099; Distributor_name: MOUSER; Distributor_part_number: 994-XAL7070-182MEB; Footprint Path: Y:\MIS_DATABASE\Library\ALTIUM_TOOL\PCB_FOOTPRINTS\Altium_Footprint_Lib.PcbLib; Height: 7.00MM; Library Path: Y:\MIS_DATABASE\Library\ALTIUM_TOOL\SCHEMATICS_PARTS\MS_DISCRETE_Library.schlib; Mfr_name: COIL CRAFT; Mfr_part_number: XAL7070-182MEB; Mistral Part No: 130019100031-R; Package: SMD; Project: BEL_QDR_BRD; RoHS: RoHS; Temperature: -40°C+125°C; Tolerance: 20%; Voltage: NA; Wattage: NA; Weight: 2100mg; Datasheet: Y:\MIS_DATABASE\DATASHEETS\DISCRETES\INDUCTORS\XAL7070_JUN19.PDF
Q2 = MOSFET_CSD17301Q5A: IC MOSFET N-CHANNEL NEXFET 30V VSON-CLIP8; Chkd/date: MANIRAJA/180820; Crtd /date: ALVY/180820; Custom_Duty: 15%; Customs_HS_Code: 85423100; Distributor_name: DIGIKEY; Distributor_part_number: 296-39994-1-ND; Footprint Path: Y:\MIS_DATABASE\Library\ALTIUM_TOOL\PCB_FOOTPRINTS\Altium_Footprint_Lib.PcbLib; Height: 1.10MM; Library Path: Y:\MIS_DATABASE\Library\ALTIUM_TOOL\SCHEMATICS_PARTS\MS_MOSFET_Library.schlib; Mfr_name: TEXAS INSTRUMENTS; Mistral Part No: 142020080002-R; Package: VSON-CLIP8; Part_type: ICS\POWER\MOSFET; Project: ISSI TDA4VM; RoHS: RoHS; Temperature: -55°C+150°C; Tolerance: NA; Voltage: NA; Wattage: NA; Weight: 44.5mg; Datasheet: Y:\MIS_DATABASE\DATASHEETS\ICS\POWER\CSD17575Q3.PDF
R81 = RESISTOR: RES 0E 1/20W 5% 0201; Chkd/date: NAVEED/301214; Crtd /date: MUDDU/120710; Custom_Duty: 15%; Customs_HS_Code: 85332119; Distributor_name: DIGIKEY; Distributor_part_number: 311-0.0NCT-ND; Footprint Path: Y:\MIS_DATABASE\Library\ALTIUM_TOOL\PCB_FOOTPRINTS\Altium_Footprint_Lib.PcbLib; Height: 0.26MM; Library Path: Y:\MIS_DATABASE\Library\ALTIUM_TOOL\SCHEMATICS_PARTS\MS_DISCRETE_Library.schlib; Manufacturer: YAGEO AMERICA; Mfr_name: YAGEO AMERICA; Mfr_part_number: RC0201JR-070RL; Mistral Part No: 110010070067-R; Package: 0201; Part_type: RESISTORS\FIXED; Project: PB_BUGBASE; RoHS: RoHS; Temperature: -55°C+125°C; Tolerance: 5%; Voltage: NA; Wattage: 1/20W; Weight: 0.17mg; Datasheet: Y:\MIS_DATABASE\DATASHEETS\RESISTORS\RCXXXXL-SER_MAR18.PDF
R397 = RESISTOR: RES 0.005E 1W 1% AUTO 1206 (HP); Chkd/date: MANIRAJA/280920; Crtd /date: ALVY/250920; Custom_Duty: 15%; Customs_HS_Code: 85332119; Distributor_name: DIGIKEY; Distributor_part_number: WSLP-.005CT-ND; Footprint Path: Y:\MIS_DATABASE\Library\ALTIUM_TOOL\PCB_FOOTPRINTS\Altium_Footprint_Lib.PcbLib; Height: 0.89MM; Library Path: Y:\MIS_DATABASE\Library\ALTIUM_TOOL\SCHEMATICS_PARTS\MS_DISCRETE_Library.schlib; Mfr_name: VISHAY; Mfr_part_number: WSLP12065L000FEA; Mistral Part No: 110020090011-R; Package: 1206; Part_type: RESISTORS\FIXED; Project: TI_J7ES_CP; RoHS: RoHS; Temperature: -65°C+170°C; Tolerance: 1%; Voltage: NA; Wattage: 1W; Weight: 16.2mg; Datasheet: Y:\MIS_DATABASE\DATASHEETS\RESISTORS\WSLP-SERIES.PDF
R417 R418 = RESISTOR: RES 0E 1/10W JUMPER 0402; Chkd/date: VASANTHA/061216; Crtd /date: NAVEED/201014; Custom_Duty: 15%; Customs_HS_Code: 85332119; Distributor_name: DIGIKEY; Distributor_part_number: P0.0JCT-ND; Footprint Path: Y:\MIS_DATABASE\Library\ALTIUM_TOOL\PCB_FOOTPRINTS\Altium_Footprint_Lib.PcbLib; Height: 0.40MM; Library Path: Y:\MIS_DATABASE\Library\ALTIUM_TOOL\SCHEMATICS_PARTS\MS_DISCRETE_Library.schlib; Mfr_name: PANASONIC-ECG; Mfr_part_number: ERJ-2GE0R00X; Mistral Part No: 110018030052-R; Package: 0402; Part_type: RESISTORS\FIXED; Project: AEGIS POM; RoHS: RoHS; Temperature: -55°C+155°C; Tolerance: NA; Voltage: NA; Wattage: 1/10W; Weight: 0.8mg; Datasheet: Y:\MIS_DATABASE\DATASHEETS\RESISTORS\PAN-ERJSER_NOV17.PDF
R420 = RESISTOR: RES 10E 1/16W 5% 0402; Chkd/date: JEBRAN/050815; Crtd /date: JEBRAN/050815; Custom_Duty: 15%; Customs_HS_Code: 85332119; Distributor_name: DIGIKEY; Distributor_part_number: 311-10JRCT-ND; Footprint Path: Y:\MIS_DATABASE\Library\ALTIUM_TOOL\PCB_FOOTPRINTS\Altium_Footprint_Lib.PcbLib; Height: 0.40MM; Library Path: Y:\MIS_DATABASE\Library\ALTIUM_TOOL\SCHEMATICS_PARTS\MS_DISCRETE_Library.schlib; Mfr_name: YAGEO AMERICA; Mfr_part_number: RC0402JR-0710RL; Mistral Part No: 110015080004-R; Package: 0402; Part_type: RESISTORS\FIXED; Project: PDLU; RoHS: RoHS; Temperature: -55°C+155°C; Tolerance: 5%; Voltage: NA; Wattage: 1/16W; Weight: 0.65mg; Datasheet: Y:\MIS_DATABASE\DATASHEETS\RESISTORS\RCXXXXL-SER_MAR18.PDF
R423 = RESISTOR: RES 44.2K 1/16W 1% 0402; Chkd/date: ALVY/041120; Crtd /date: ALVY/041120; Custom_Duty: 15%; Customs_HS_Code: 85332119; Distributor_name: DIGIKEY; Distributor_part_number: 541-4106-1-ND; Footprint Path: Y:\MIS_DATABASE\Library\ALTIUM_TOOL\PCB_FOOTPRINTS\Altium_Footprint_Lib.PcbLib; Height: 0.35MM; Library Path: Y:\MIS_DATABASE\Library\ALTIUM_TOOL\SCHEMATICS_PARTS\MS_DISCRETE_Library.schlib; Mfr_name: VISHAY; Mfr_part_number: CRCW040244K2FKEDC; Mistral Part No: 110010070032-R; Package: 0402; Part_type: RESISTORS\FIXED; Project: TI_J7ES_EVM_FUSION2_SER_CAP; RoHS: RoHS; Temperature: -55°C+155°C; Tolerance: 1%; Voltage: NA; Wattage: 1/16W; Weight: 0.65mg; Datasheet: Y:\MIS_DATABASE\DATASHEETS\RESISTORS\CRCW_C-SER.PDF
R441 = RESISTOR: RES 2.05K 1/16W 1% 0402; Chkd/date: MANIRAJA/261020; Crtd /date: MANIRAJA/261020; Custom_Duty: 15%; Customs_HS_Code: 85332119; Distributor_name: DIGIKEY; Distributor_part_number: 541-2.05KLCT-ND; Footprint Path: Y:\MIS_DATABASE\Library\ALTIUM_TOOL\PCB_FOOTPRINTS\Altium_Footprint_Lib.PcbLib; Height: 0.40MM; Library Path: Y:\MIS_DATABASE\Library\ALTIUM_TOOL\SCHEMATICS_PARTS\MS_DISCRETE_Library.schlib; Mfr_name: VISHAY; Mfr_part_number: CRCW04022K05FKED; Mistral Part No: 110020100049-R; Package: 0402; Part_type: RESISTORS\FIXED; Project: TM2_1W_SEN10RO; RoHS: RoHS; Temperature: -55°C+155°C; Tolerance: 1%; Voltage: NA; Wattage: 1/16W; Weight: 0.65mg; Datasheet: Y:\MIS_DATABASE\DATASHEETS\RESISTORS\CRCW0603.PDF
R443 R444 = RESISTOR: RES 10K 1/16W 5% 0402; Chkd/date: VASANTHA/061216; Crtd /date: MAZHAR/230805; Custom_Duty: 15%; Customs_HS_Code: 85332119; Distributor_name: DIGIKEY; Distributor_part_number: 311-10KJRCT-ND; Footprint Path: Y:\MIS_DATABASE\Library\ALTIUM_TOOL\PCB_FOOTPRINTS\Altium_Footprint_Lib.PcbLib; Height: 0.40MM; Library Path: Y:\MIS_DATABASE\Library\ALTIUM_TOOL\SCHEMATICS_PARTS\MS_DISCRETE_Library.schlib; Mfr_name: YAGEO AMERICA; Mfr_part_number: RC0402JR-0710KL; Mistral Part No: 110011060021-R; Package: 0402; Part_type: RESISTORS\FIXED; Project: HSE; RoHS: RoHS; Temperature: -55°C+155°C; Tolerance: 5%; Voltage: NA; Wattage: 1/16W; Weight: 0.65mg; Datasheet: Y:\MIS_DATABASE\DATASHEETS\RESISTORS\RCXXXXL-SER_MAR18.PDF
TP110-TP114 = TESTPOINT: TESTPOINT 1.0MM DRILL PTH; Chkd/date: MAZHAR/271211; Crtd /date: SHREESHAIL/041005; Distributor_name: NA; Distributor_part_number: NA; Height: NA; Mfr_name: LOCAL; Mistral Part No: 130009030938; Package: THRU-HOLE; Project: HSE; Datasheet: NA
TP115-TP117 = TESTPOINT: TESTPOINT CIR 40 SMD; Chkd/date: MAZHAR/190505; Crtd /date: MAZHAR/190505; Distributor_name: NA; Distributor_part_number: NA; Footprint Path: Y:\MIS_DATABASE\Library\ALTIUM_TOOL\PCB_FOOTPRINTS\Altium_Footprint_Lib.PcbLib; Height: NA; Library Path: Y:\MIS_DATABASE\Library\ALTIUM_TOOL\SCHEMATICS_PARTS\MS_DISCRETE_Library.schlib; MECHANICAL 3D STEP FILE: NA; Mfr_name: LOCAL; Mistral Part No: 130009030933; Package: SMD; Project: RAINIER-3; RoHS: NA; Temperature: NA; Tolerance: NA; Voltage: NA; Wattage: NA; Weight: NA; Datasheet: NA
U39 = MOSFET_CSD18501Q5A: IC MOSFET N-CHANNEL 30V 47A VSON8; Chkd/date: VASANTHA/13115; Crtd /date: VASANTHA/13115; Custom_Duty: 15%; Customs_HS_Code: 85423100; Distributor_name: DIGIKEY; Distributor_part_number: 296-27210-1-ND; Footprint Path: Y:\MIS_DATABASE\Library\ALTIUM_TOOL\PCB_FOOTPRINTS\Altium_Footprint_Lib.PcbLib; Height: 1.10MM; Library Path: Y:\MIS_DATABASE\Library\ALTIUM_TOOL\SCHEMATICS_PARTS\MS_MOSFET_Library.schlib; Mfr_name: TEXAS INSTRUMENTS; Mistral Part No: 142015110013-R; Package: SON8; Part_type: ICS\POWER\MOSFET; Project: OCTASIC_3600; RoHS: RoHS; Temperature: -55°C+150°C; Tolerance: NA; Voltage: 30V; Wattage: NA; Weight: NA; Datasheet: Y:\MIS_DATABASE\DATASHEETS\DISCRETES\TRANSISTORS_FETS\CSD17308Q3.PDF
U89 = LM5141RGET_VQFN24: IC WIDE I/P RANGE SYNCHRONOUS BUCK CONTROLLER VQFN24; Automotive Alternate_mfr_name: TEXAS INSTRUMENTS; Chkd/date: MANIRAJA/031018; Crtd /date: MANIRAJA/031018; Custom_Duty: 15%; Customs_HS_Code: 85423100; Distributor_name: DIGIKEY; Distributor_part_number: 296-44870-1-ND; Footprint Path: Y:\MIS_DATABASE\Library\ALTIUM_TOOL\PCB_FOOTPRINTS\Altium_Footprint_Lib.PcbLib; Height: 1.00MM; Library Path: Y:\MIS_DATABASE\Library\ALTIUM_TOOL\SCHEMATICS_PARTS\MS_MISCPOWER_Library.schlib; Mfr_name: TEXAS INSTRUMENTS; Mistral Part No: 142018100002-R; Package: VQFN24; Part_type: ICS\POWER\CONTROL; Project: TI_J7ES_EVM_CP; RoHS: RoHS; Temperature: -40°C+150°C; Tolerance: NA; Voltage: NA; Wattage: NA; Weight: NA; Datasheet: Y:\MIS_DATABASE\DATASHEETS\ICS\POWER\LM5141-Q1.PDF

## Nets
DGND: C114.2 C129.2 C136.2 C138.2 C139.2 C140.2 C141.2 C230.2 C242.2 C249.2 C256.2 C326.2 C339.2 C403.2 C404.1 C405.1 C413.2 C420.2 C421.1 C427.2 C429.2 C432.2 C433.2 C446.2 C447.2 C448.2 Q2.1(1S) Q2.2(2S) Q2.3(3S) R195.2 R357.2 R423.2 R469.2 TP110.1(TP) TP111.1(TP) TP112.1(TP) TP113.1(TP) TP114.1(TP) TP115.1(TP) TP116.1(TP) TP117.1(TP) U43.4(GND) U43.10(PGND) U43.15(VSEL) U63.2(GND) U63.5(EP) U65.2(GND) U65.5(EP) U81.4(GND) U89.3(AGND) U89.6(OSC) U89.9(PGND) U89.16(VCCX) U89.25(EP) U89.A1 U89.A2 U89.A3 U89.A4 ; also on sheet 9 12 13 14 15 16 17 18 19 20 21 22 23 24 25 26 27 28 29 30 31 32 33 34 35 36 37 38 39 40 41 42 43
VCC2V5_PG: R329.1 R360.1 U81.2(PG)
VCC_3V3_MAIN: C403.1 C404.2 C405.2 R397.2 R443.2 TP46.1(TP) U89.17(VOUT) ; also on sheet 12 14 25
VCC_3V3_MAIN_PG: R361.1 R443.1 U89.21(PG) ; also on sheet 12
VCC_3V3_SYS: C339.1 U81.6(VIN) ; also on sheet 9 12 13 17 18 19 21 22 23 25 26 28 29 30 32 33 34 35 36 37 38 39 40 41 42
VCC_5V0: C138.1 C139.1 C446.1 C447.1 R196.2 R200.1 TP73.1(TP) U43.7(VOUT) ; also on sheet 9 32 34 37 40
VCC_5V0_EN: R201.2 U43.14(EN) ; also on sheet 12
VCC_5V0_FB: R195.1 R200.2 U43.5(FB)
VCC_5V0_PG: R196.1 R197.2 ; also on sheet 41
VCC_LM5141: C413.1 D9.2(ANODE) U89.10(VCC)
VDD_1V0: C230.1 TP17.1(TP) U63.1(OUT) ; also on sheet 22 23
VDD_1V2: C249.1 TP13.1(TP) U65.1(OUT) ; also on sheet 40
VDD_2V5: C242.1 C256.1 C326.1 C327.1 L9.2 R325.1 R358.1 R360.2 TP29.1(TP) U63.4(IN) U65.4(IN) ; also on sheet 22 23
VDD_2V5_FB: C327.2 R357.1 R358.2 U81.3(FB)
VDDA_LM5141: C421.2 U89.1(DEMB) U89.2(VDDA) U89.5(DITH) U89.19(FB)
COMP_LM5141: C433.1 R441.1 U89.20(COMP)
CS_LM5141: L10.2 R397.1 U89.18(CS)
EN_LM5141_ON: R81.2 R444.1 U89.23(EN)
ETH_CAN_INH_PREREG: R81.1 ; also on sheet 33
HB_LM5141: C412.2 D9.1(CATHODE) U89.11(HB)
HO_LM5141: R420.1 U89.13(HO)
HOL_LM5141: R420.2 U39.4(GATE) U89.14(HOL)
LO_LM5141: R417.1 U89.8(LO)
LOL_LM5141: R418.1 U89.7(LOL)
RES_LM5141: C427.1 U89.24(RES)
RT_LM5141: R423.1 U89.4(RT)
SS_LM5141: C429.1 U89.22(SS)
SW_2V5: L9.1 U81.5(SW)
SW_LM5141: C412.1 L10.1 Q2.5(D) U39.1(S1) U39.2(S2) U39.3(S3) U89.12(SW)
TEST_POWERDOWN: R201.1 ; also on sheet 12 25 27
VMAIN: C114.1 C129.1 C140.1 C141.1 C420.1 C448.1 R199.1 R444.2 TP68.1(TP) U39.5(D1) U43.12(VIN) U89.15(VIN) ; also on sheet 9 25
N20506305: L8.1 U43.11(L1)
N20506307: L8.2 U43.9(L2)
N20506388: R469.1 U43.6(FB2)
N20506390: R197.1 U43.2(PG)
N20506392: R199.2 U43.1(PS/SYNC)
N20506511: C136.1 U43.3(VAUX)
N22424368: C432.1 R441.2
N22424482: Q2.4(G) R417.2 R418.2
N22441821: R329.2 U63.3(EN)
N22441998: R361.2 U81.1(EN)
N22442187: R325.2 U65.3(EN)

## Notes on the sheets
sheet 10
- PERIPHERAL POWER SUPPLIES - 1
- D-Note :-
  Add a Jumper or OR for isolation
  or Current measurement for
  preproduction board
- VinMin = 4.5V
  VinMax = 15V
  Vout = 5V @ 2A
- SILK SCREEN : VCC_5V0
- 2.5V, 1.0 AMP SUPPLY
- ETHERNET PHY
- SILK SCREEN : VDD_2V5
- PERIPHERAL SUPPLY - ETHERNET PHY
- 1.0V, 0.5 AMP SUPPLY
- 1.2V, 0.5 AMP SUPPLY
- HDMI TRANSMITTER
- SILK SCREEN : VDD_1V0
sheet 11
- PERIPHERAL POWER SUPPLIES - 2
- 3.3V, 10.0 AMPS SUPPLY
- VinMin = 4.5V
  VinMax = 15V
  Vout = 3.3V @ 10A
- D-Note :-
  Add a Jumper or 0R for
  isolation or Current
  measurement for
  preproduction board
- D-Note :-
  Follow kelvin
  connection for
  current sense
- @@ ALWAYS ON
- CAD Note: Short LM5141_AGND and DGND at single point
- GND TEST POINTS
